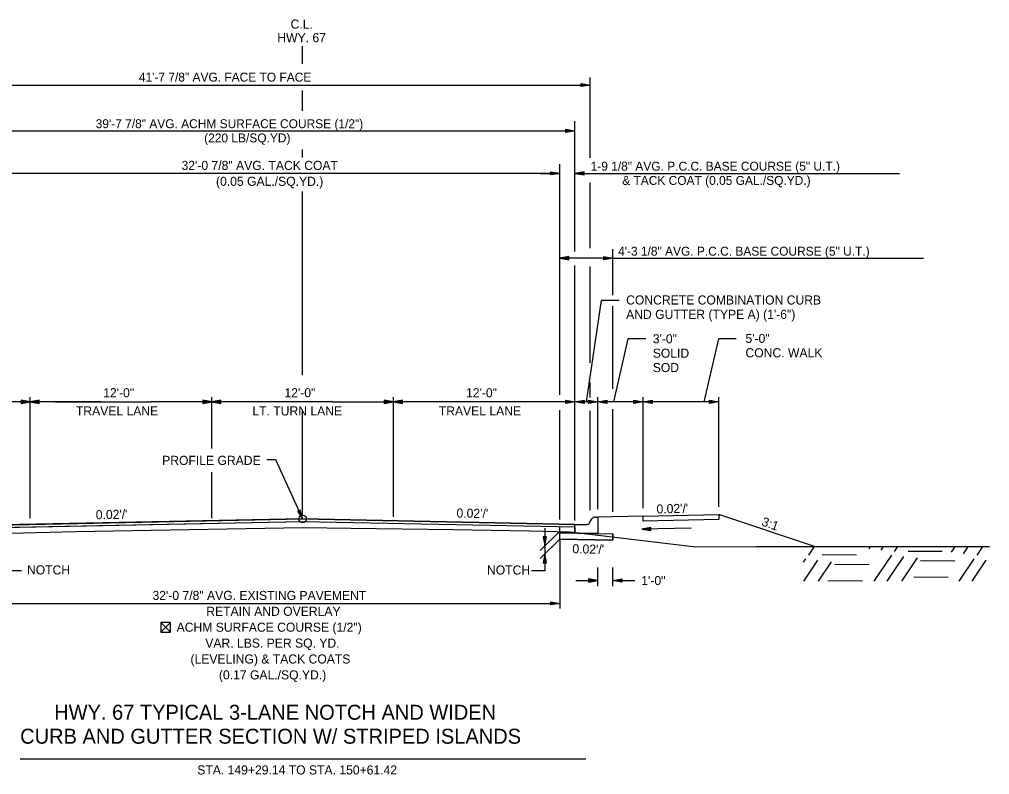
# Model space of a CAD drawing. Extents: x 1001270 to 1003428, y 1840152 to 1842912.
# Drawn here: x 1001595.7 to 1001659.8, y 1842014.9 to 1842064.9 of the extents above; entities that cross this region are included whole.
import ezdxf

# ---------------------------------------------------------------- set-up
doc = ezdxf.new("R2010")
doc.units = 0
for name, color, linetype in [('10', 7, 'Continuous'), ('19', 7, 'Continuous'), ('20', 7, 'Continuous'), ('8', 7, 'Continuous')]:
    doc.layers.add(name, color=color, linetype=linetype)

# ---------------------------------------------------------------- blocks, each defined once
blk = doc.blocks.new('TM')
at = {"layer": '8'}
for p, q in [((-120.309, 21.181), (-119.787, -20.829)), ((0, 0), (-120.309, 21.181)), ((-31.382, 2.945), (-120.176, 10.512)), ((-119.787, -20.829), (0, 0)), ((-119.911, -10.826), (-31.307, -3.057))]:
    blk.add_line(p, q, dxfattribs=at)

msp = doc.modelspace()

# ---------------------------------------------------------------- linework, layer by layer
at = {"layer": '10'}
for p, q in [((1001605.092, 1842024.997), (1001605.733, 1842024.355)), ((1001605.733, 1842024.997), (1001605.092, 1842024.355)), ((1001605.473, 1842024.355), (1001605.485, 1842024.355))]:
    msp.add_line(p, q, dxfattribs=at)
msp.add_lwpolyline([(1001605.485, 1842024.355), (1001605.733, 1842024.355), (1001605.733, 1842024.997), (1001605.092, 1842024.997), (1001605.092, 1842024.355), (1001605.473, 1842024.355)], dxfattribs=at)
at = {"layer": '19'}
for p, q in [((1001614.45, 1842061.908), (1001614.45, 1842063.094)), ((1001633.451, 1842055.7), (1001633.451, 1842061.015)), ((1001588.118, 1842060.512), (1001633.451, 1842060.512)), ((1001614.45, 1842058.815), (1001614.45, 1842060.143)), ((1001632.851, 1842060.407), (1001632.851, 1842060.617)), ((1001632.851, 1842060.617), (1001633.451, 1842060.512)), ((1001632.851, 1842060.562), (1001633.291, 1842060.527)), ((1001633.451, 1842060.512), (1001632.851, 1842060.407)), ((1001633.291, 1842060.497), (1001632.851, 1842060.457)), ((1001632.45, 1842049.512), (1001632.45, 1842058.137)), ((1001589.117, 1842057.485), (1001632.45, 1842057.485)), ((1001631.851, 1842057.38), (1001631.851, 1842057.59)), ((1001631.851, 1842057.59), (1001632.451, 1842057.485)), ((1001631.851, 1842057.535), (1001632.291, 1842057.5)), ((1001632.451, 1842057.485), (1001631.851, 1842057.38)), ((1001632.291, 1842057.47), (1001631.851, 1842057.43)), ((1001614.45, 1842055.714), (1001614.45, 1842056.258)), ((1001631.447, 1842040.046), (1001631.447, 1842055.277)), ((1001594.117, 1842054.679), (1001631.446, 1842054.679)), ((1001630.118, 1842054.677), (1001631.447, 1842054.677)), ((1001630.846, 1842054.574), (1001630.846, 1842054.784)), ((1001630.846, 1842054.784), (1001631.446, 1842054.679)), ((1001630.846, 1842054.729), (1001631.286, 1842054.694)), ((1001631.446, 1842054.679), (1001630.846, 1842054.574)), ((1001631.286, 1842054.664), (1001630.846, 1842054.624)), ((1001630.847, 1842054.572), (1001630.847, 1842054.782)), ((1001630.847, 1842054.782), (1001631.447, 1842054.677)), ((1001630.847, 1842054.727), (1001631.287, 1842054.692)), ((1001631.447, 1842054.677), (1001630.847, 1842054.572)), ((1001631.287, 1842054.662), (1001630.847, 1842054.622)), ((1001633.049, 1842054.782), (1001632.449, 1842054.677)), ((1001632.449, 1842054.677), (1001633.049, 1842054.572)), ((1001632.451, 1842054.677), (1001653.897, 1842054.677)), ((1001633.049, 1842054.727), (1001632.609, 1842054.692)), ((1001632.609, 1842054.662), (1001633.049, 1842054.622)), ((1001633.049, 1842054.572), (1001633.049, 1842054.782)), ((1001633.451, 1842049.734), (1001633.451, 1842054.073)), ((1001614.45, 1842041.341), (1001614.45, 1842053.475)), ((1001632.047, 1842049.182), (1001631.447, 1842049.077)), ((1001632.047, 1842049.127), (1001631.607, 1842049.092)), ((1001632.047, 1842048.972), (1001632.047, 1842049.182)), ((1001634.35, 1842048.972), (1001634.35, 1842049.182)), ((1001634.35, 1842049.182), (1001634.95, 1842049.077)), ((1001634.35, 1842049.127), (1001634.79, 1842049.092)), ((1001634.95, 1842046.63), (1001634.95, 1842049.677)), ((1001634.95, 1842049.077), (1001631.447, 1842049.077)), ((1001631.447, 1842049.077), (1001632.047, 1842048.972)), ((1001631.607, 1842049.062), (1001632.047, 1842049.022)), ((1001632.45, 1842031.727), (1001632.45, 1842048.58)), ((1001633.451, 1842042.162), (1001633.451, 1842048.53)), ((1001634.95, 1842049.077), (1001634.35, 1842048.972)), ((1001634.79, 1842049.062), (1001634.35, 1842049.022)), ((1001634.95, 1842049.077), (1001655.48, 1842049.077)), ((1001634.181, 1842046.267), (1001633.193, 1842039.576)), ((1001635.36, 1842046.267), (1001634.181, 1842046.267)), ((1001634.95, 1842040.43), (1001634.95, 1842045.895)), ((1001635.945, 1842043.733), (1001634.988, 1842039.576)), ((1001637.124, 1842043.733), (1001635.945, 1842043.733)), ((1001641.927, 1842043.733), (1001640.971, 1842039.576)), ((1001643.106, 1842043.733), (1001641.927, 1842043.733)), ((1001633.451, 1842039.868), (1001633.451, 1842040.863)), ((1001601.117, 1842039.576), (1001589.117, 1842039.576)), ((1001595.85, 1842039.681), (1001595.85, 1842039.471)), ((1001596.45, 1842039.576), (1001595.85, 1842039.681)), ((1001596.29, 1842039.591), (1001595.85, 1842039.626)), ((1001595.85, 1842039.471), (1001596.45, 1842039.576)), ((1001595.85, 1842039.521), (1001596.29, 1842039.561)), ((1001596.45, 1842031.887), (1001596.45, 1842039.876)), ((1001597.05, 1842039.681), (1001596.45, 1842039.576)), ((1001596.45, 1842039.576), (1001597.05, 1842039.471)), ((1001597.05, 1842039.626), (1001596.61, 1842039.591)), ((1001596.61, 1842039.561), (1001597.05, 1842039.521)), ((1001597.05, 1842039.471), (1001597.05, 1842039.681)), ((1001598.132, 1842039.576), (1001604.45, 1842039.576)), ((1001616.45, 1842039.576), (1001604.45, 1842039.576)), ((1001607.85, 1842039.681), (1001607.85, 1842039.471)), ((1001608.45, 1842039.576), (1001607.85, 1842039.681)), ((1001608.29, 1842039.591), (1001607.85, 1842039.626)), ((1001607.85, 1842039.471), (1001608.45, 1842039.576)), ((1001607.85, 1842039.521), (1001608.29, 1842039.561)), ((1001608.45, 1842036.493), (1001608.45, 1842039.876)), ((1001609.05, 1842039.681), (1001608.45, 1842039.576)), ((1001608.45, 1842039.576), (1001609.05, 1842039.471)), ((1001609.05, 1842039.626), (1001608.61, 1842039.591)), ((1001608.61, 1842039.561), (1001609.05, 1842039.521)), ((1001609.05, 1842039.471), (1001609.05, 1842039.681)), ((1001616.45, 1842039.576), (1001620.45, 1842039.576)), ((1001619.85, 1842039.681), (1001619.85, 1842039.471)), ((1001620.45, 1842039.576), (1001619.85, 1842039.681)), ((1001620.29, 1842039.591), (1001619.85, 1842039.626)), ((1001619.85, 1842039.471), (1001620.45, 1842039.576)), ((1001619.85, 1842039.521), (1001620.29, 1842039.561)), ((1001620.45, 1842031.967), (1001620.45, 1842039.876)), ((1001621.05, 1842039.681), (1001620.45, 1842039.576)), ((1001632.45, 1842039.576), (1001620.45, 1842039.576)), ((1001620.45, 1842039.576), (1001621.05, 1842039.471)), ((1001621.05, 1842039.626), (1001620.61, 1842039.591)), ((1001620.61, 1842039.561), (1001621.05, 1842039.521)), ((1001621.05, 1842039.471), (1001621.05, 1842039.681)), ((1001631.85, 1842039.471), (1001631.85, 1842039.681)), ((1001631.85, 1842039.681), (1001632.45, 1842039.576)), ((1001631.85, 1842039.626), (1001632.29, 1842039.591)), ((1001632.45, 1842039.576), (1001631.85, 1842039.471)), ((1001632.29, 1842039.561), (1001631.85, 1842039.521)), ((1001632.45, 1842031.727), (1001632.45, 1842039.876)), ((1001632.45, 1842039.576), (1001633.05, 1842039.681)), ((1001641.95, 1842039.576), (1001632.45, 1842039.576)), ((1001633.05, 1842039.471), (1001632.45, 1842039.576)), ((1001632.61, 1842039.591), (1001633.05, 1842039.626)), ((1001633.05, 1842039.521), (1001632.61, 1842039.561)), ((1001633.05, 1842039.681), (1001633.05, 1842039.471)), ((1001633.35, 1842039.471), (1001633.35, 1842039.681)), ((1001633.35, 1842039.681), (1001633.95, 1842039.576)), ((1001633.35, 1842039.626), (1001633.79, 1842039.591)), ((1001633.95, 1842039.576), (1001633.35, 1842039.471)), ((1001633.79, 1842039.561), (1001633.35, 1842039.521)), ((1001633.95, 1842032.477), (1001633.95, 1842039.876)), ((1001633.95, 1842039.576), (1001634.55, 1842039.681)), ((1001634.55, 1842039.471), (1001633.95, 1842039.576)), ((1001634.11, 1842039.591), (1001634.55, 1842039.626)), ((1001634.55, 1842039.521), (1001634.11, 1842039.561)), ((1001634.55, 1842039.681), (1001634.55, 1842039.471)), ((1001636.35, 1842039.471), (1001636.35, 1842039.681)), ((1001636.35, 1842039.681), (1001636.95, 1842039.576)), ((1001636.35, 1842039.626), (1001636.79, 1842039.591)), ((1001636.95, 1842039.576), (1001636.35, 1842039.471)), ((1001636.79, 1842039.561), (1001636.35, 1842039.521)), ((1001636.95, 1842032.537), (1001636.95, 1842039.876)), ((1001636.95, 1842039.576), (1001637.55, 1842039.681)), ((1001637.55, 1842039.471), (1001636.95, 1842039.576)), ((1001637.11, 1842039.591), (1001637.55, 1842039.626)), ((1001637.55, 1842039.521), (1001637.11, 1842039.561)), ((1001637.55, 1842039.681), (1001637.55, 1842039.471)), ((1001641.35, 1842039.471), (1001641.35, 1842039.681)), ((1001641.35, 1842039.681), (1001641.95, 1842039.576)), ((1001641.35, 1842039.626), (1001641.79, 1842039.591)), ((1001641.95, 1842039.576), (1001641.35, 1842039.471)), ((1001641.79, 1842039.561), (1001641.35, 1842039.521)), ((1001641.95, 1842032.637), (1001641.95, 1842039.876)), ((1001614.45, 1842032.087), (1001614.45, 1842039.014)), ((1001631.447, 1842031.8), (1001631.447, 1842039.023)), ((1001633.451, 1842032.407), (1001633.451, 1842038.992)), ((1001634.95, 1842032.311), (1001634.95, 1842039.087)), ((1001608.45, 1842031.887), (1001608.45, 1842034.922)), ((1001589.117, 1842031.33), (1001614.45, 1842031.837)), ((1001614.296, 1842032.426), (1001614.106, 1842032.339)), ((1001614.106, 1842032.339), (1001614.45, 1842031.837)), ((1001614.149, 1842032.355), (1001614.369, 1842031.977)), ((1001614.393, 1842031.986), (1001614.249, 1842032.399)), ((1001614.45, 1842031.837), (1001614.296, 1842032.426)), ((1001614.45, 1842031.837), (1001632.45, 1842031.477)), ((1001633.421, 1842031.586), (1001633.567, 1842031.838)), ((1001633.783, 1842031.962), (1001633.95, 1842031.962)), ((1001636.951, 1842032.023), (1001633.95, 1842031.962)), ((1001633.95, 1842031.962), (1001633.95, 1842031.629)), ((1001636.951, 1842032.022), (1001641.95, 1842032.122)), ((1001636.951, 1842031.689), (1001636.951, 1842032.022)), ((1001636.951, 1842032.022), (1001636.951, 1842032.022)), ((1001648.286, 1842030.01), (1001641.95, 1842032.122)), ((1001641.95, 1842032.122), (1001641.95, 1842031.789)), ((1001589.117, 1842031.164), (1001614.45, 1842031.67)), ((1001614.45, 1842031.67), (1001632.45, 1842031.31)), ((1001631.447, 1842030.497), (1001631.447, 1842031.33)), ((1001631.447, 1842031.33), (1001632.45, 1842031.31)), ((1001631.447, 1842030.914), (1001631.447, 1842031.33)), ((1001631.447, 1842031.33), (1001631.447, 1842031.33)), ((1001632.45, 1842031.477), (1001632.734, 1842031.471)), ((1001632.45, 1842031.31), (1001632.45, 1842030.897)), ((1001632.734, 1842031.471), (1001632.734, 1842031.471)), ((1001632.734, 1842031.471), (1001632.734, 1842031.471)), ((1001632.734, 1842031.471), (1001633.2, 1842031.462)), ((1001633.95, 1842031.629), (1001633.95, 1842031.447)), ((1001633.95, 1842031.447), (1001633.95, 1842030.867)), ((1001641.95, 1842031.789), (1001636.951, 1842031.689)), ((1001631.447, 1842031.028), (1001630.147, 1842029.755)), ((1001630.561, 1842030.658), (1001630.351, 1842030.658)), ((1001630.351, 1842030.658), (1001630.456, 1842030.058)), ((1001630.406, 1842030.658), (1001630.441, 1842030.218)), ((1001630.456, 1842030.058), (1001630.561, 1842030.658)), ((1001630.471, 1842030.218), (1001630.511, 1842030.658)), ((1001631.447, 1842030.914), (1001632.45, 1842030.894)), ((1001631.447, 1842030.914), (1001634.95, 1842030.847)), ((1001631.447, 1842030.497), (1001631.447, 1842030.914)), ((1001631.447, 1842030.914), (1001631.447, 1842030.914)), ((1001632.45, 1842030.897), (1001631.447, 1842030.914)), ((1001633.95, 1842030.867), (1001632.45, 1842030.897)), ((1001633.95, 1842030.867), (1001634.95, 1842030.847)), ((1001634.95, 1842030.427), (1001634.95, 1842030.847)), ((1001634.95, 1842030.847), (1001634.95, 1842030.427)), ((1001631.447, 1842030.497), (1001630.147, 1842029.225)), ((1001631.447, 1842030.497), (1001631.447, 1842025.91)), ((1001631.447, 1842030.497), (1001634.95, 1842030.427)), ((1001634.95, 1842030.427), (1001631.447, 1842030.497)), ((1001647.895, 1842029.436), (1001648.286, 1842030.019)), ((1001651.88, 1842029.87), (1001651.986, 1842030.02)), ((1001652.675, 1842029.778), (1001652.841, 1842030.022)), ((1001653.57, 1842029.686), (1001653.796, 1842030.025)), ((1001657.334, 1842029.63), (1001657.596, 1842030.026)), ((1001658.129, 1842029.538), (1001658.461, 1842030.027)), ((1001659.024, 1842029.446), (1001659.405, 1842030.02)), ((1001630.456, 1842029.528), (1001630.351, 1842028.928)), ((1001630.441, 1842029.368), (1001630.401, 1842028.928)), ((1001630.561, 1842028.928), (1001630.456, 1842029.528)), ((1001630.506, 1842028.928), (1001630.471, 1842029.368)), ((1001648.783, 1842029.475), (1001651.043, 1842029.453)), ((1001652.232, 1842027.723), (1001653.384, 1842029.444)), ((1001653.087, 1842027.725), (1001654.179, 1842029.352)), ((1001654.042, 1842027.727), (1001655.074, 1842029.26)), ((1001654.458, 1842029.715), (1001656.718, 1842029.704)), ((1001630.351, 1842028.928), (1001630.561, 1842028.928)), ((1001633.95, 1842027.394), (1001633.95, 1842028.632)), ((1001634.95, 1842027.394), (1001634.95, 1842028.632)), ((1001647.555, 1842028.968), (1001647.709, 1842029.193)), ((1001647.577, 1842027.719), (1001648.504, 1842029.102)), ((1001648.532, 1842027.721), (1001649.399, 1842029.009)), ((1001649.623, 1842028.846), (1001651.883, 1842028.824)), ((1001655.288, 1842029.087), (1001657.558, 1842029.074)), ((1001657.842, 1842027.728), (1001658.838, 1842029.204)), ((1001658.697, 1842027.731), (1001659.633, 1842029.112)), ((1001595.023, 1842028.425), (1001595.887, 1842028.425)), ((1001630.456, 1842028.4), (1001629.582, 1842028.4)), ((1001654.846, 1842028.017), (1001657.105, 1842027.995)), ((1001632.501, 1842027.772), (1001633.95, 1842027.772)), ((1001632.501, 1842027.772), (1001633.95, 1842027.772)), ((1001633.35, 1842027.877), (1001633.35, 1842027.667)), ((1001633.95, 1842027.772), (1001633.35, 1842027.877)), ((1001633.35, 1842027.877), (1001633.35, 1842027.667)), ((1001633.95, 1842027.772), (1001633.35, 1842027.877)), ((1001633.79, 1842027.787), (1001633.35, 1842027.822)), ((1001633.79, 1842027.787), (1001633.35, 1842027.822)), ((1001633.35, 1842027.667), (1001633.95, 1842027.772)), ((1001633.35, 1842027.667), (1001633.95, 1842027.772)), ((1001633.35, 1842027.717), (1001633.79, 1842027.757)), ((1001633.35, 1842027.717), (1001633.79, 1842027.757)), ((1001634.95, 1842027.772), (1001635.55, 1842027.877)), ((1001634.95, 1842027.772), (1001635.55, 1842027.877)), ((1001635.55, 1842027.667), (1001634.95, 1842027.772)), ((1001634.95, 1842027.772), (1001636.399, 1842027.772)), ((1001635.55, 1842027.667), (1001634.95, 1842027.772)), ((1001634.95, 1842027.772), (1001636.399, 1842027.772)), ((1001635.11, 1842027.787), (1001635.55, 1842027.822)), ((1001635.11, 1842027.787), (1001635.55, 1842027.822)), ((1001635.55, 1842027.717), (1001635.11, 1842027.757)), ((1001635.55, 1842027.717), (1001635.11, 1842027.757)), ((1001635.55, 1842027.877), (1001635.55, 1842027.667)), ((1001635.55, 1842027.877), (1001635.55, 1842027.667)), ((1001649.17, 1842027.766), (1001651.441, 1842027.754)), ((1001594.117, 1842026.258), (1001631.447, 1842026.258)), ((1001630.847, 1842026.153), (1001630.847, 1842026.363)), ((1001630.847, 1842026.363), (1001631.447, 1842026.258)), ((1001630.847, 1842026.308), (1001631.287, 1842026.273)), ((1001631.447, 1842026.258), (1001630.847, 1842026.153)), ((1001631.287, 1842026.243), (1001630.847, 1842026.203)), ((1001595.788, 1842015.991), (1001633.174, 1842015.991)), ((1001599.622, 1842015.991), (1001629.354, 1842015.991))]:
    msp.add_line(p, q, dxfattribs=at)
for points in [[(1001612.084, 1842035.769), (1001612.654, 1842035.769), (1001614.45, 1842031.837)], [(1001560.23, 1842034.4), (1001572.889, 1842034.386), (1001575.072, 1842034.166), (1001576.768, 1842033.894), (1001578.883, 1842032.583), (1001582.074, 1842031.462), (1001587.364, 1842031.607), (1001587.963, 1842031.615), (1001588.367, 1842031.161), (1001589.117, 1842031.195), (1001589.117, 1842030.738), (1001599.45, 1842030.999), (1001614.46, 1842031.276)], [(1001614.46, 1842031.276), (1001617.671, 1842031.225), (1001624.385, 1842031.132), (1001629.45, 1842031.046), (1001632.131, 1842030.984)], [(1001630.456, 1842031.224), (1001630.456, 1842028.4)], [(1001632.45, 1842030.897), (1001632.45, 1842031.061), (1001632.45, 1842031.31), (1001632.45, 1842031.477)], [(1001632.131, 1842030.984), (1001640.43, 1842029.994), (1001644.452, 1842030.007), (1001659.849, 1842030.009)]]:
    msp.add_lwpolyline(points, dxfattribs=at)
msp.add_lwpolyline([(1001614.45, 1842031.837), (1001589.117, 1842031.33), (1001589.117, 1842031.164), (1001614.45, 1842031.67), (1001632.45, 1842031.31), (1001632.45, 1842031.477)], close=True, dxfattribs=at)
msp.add_circle((1001614.45, 1842031.837), 0.25, dxfattribs=at)
for centre, start, end in [((1001633.783, 1842031.712), 90, 149.8381), ((1001633.205, 1842031.712), 268.85424, 329.83652)]:
    msp.add_arc(centre, 0.25, start, end, dxfattribs=at)
at = {"layer": '20'}
msp.add_line((1001640.131, 1842031.221), (1001636.861, 1842031.158), dxfattribs=at)

# ---------------------------------------------------------------- block references
at = {"layer": '19', "xscale": 0.0050063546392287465, "yscale": 0.005006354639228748, "rotation": -178.8817897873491}
msp.add_blockref('TM', (1001636.86, 1842031.161), dxfattribs=at)

# ---------------------------------------------------------------- texts
at = {"layer": '19'}
for s, height, p in [('C.L.', 0.6, (1001613.662, 1842064.243)), ('HWY. 67', 0.6, (1001612.783, 1842063.343)), ('41\'-7 7/8" AVG. FACE TO FACE', 0.59001, (1001603.633, 1842060.743)), ('39\'-7 7/8" AVG. ACHM SURFACE COURSE (1/2")', 0.59001, (1001600.779, 1842057.663)), ('(220 LB/SQ.YD)', 0.59001, (1001607.948, 1842056.723)), ('1-9 1/8" AVG. P.C.C. BASE COURSE (5" U.T.)', 0.59001, (1001633.486, 1842054.855)), ('& TACK COAT (0.05 GAL./SQ.YD.)', 0.59001, (1001635.572, 1842053.915)), ('4\'-3 1/8" AVG. P.C.C. BASE COURSE (5" U.T.)', 0.59001, (1001635.297, 1842049.236)), ('CONCRETE COMBINATION CURB', 0.6, (1001635.832, 1842046.009)), ('AND GUTTER (TYPE A) (1\'-6")', 0.6, (1001635.832, 1842045.059)), ('3\'-0"', 0.6, (1001637.59, 1842043.441)), ('5\'-0"', 0.6, (1001643.717, 1842043.468)), ('SOLID ', 0.6, (1001637.59, 1842042.491)), ('CONC. WALK', 0.6, (1001643.717, 1842042.518)), ('SOD', 0.6, (1001637.59, 1842041.541)), ('12\'-0"', 0.6, (1001601.275, 1842039.876)), ('12\'-0"', 0.6, (1001613.252, 1842039.876)), ('12\'-0"', 0.6, (1001625.252, 1842039.876)), ('TRAVEL LANE', 0.6, (1001599.473, 1842038.676)), ('LT. TURN LANE', 0.6, (1001611.133, 1842038.676)), ('TRAVEL LANE', 0.6, (1001623.45, 1842038.676)), ('PROFILE GRADE', 0.6, (1001605.171, 1842035.407)), ('NOTCH', 0.6, (1001596.238, 1842028.168)), ('NOTCH', 0.6, (1001626.636, 1842028.162))]:
    msp.add_text(s, height=height, dxfattribs=at).set_placement(p)
for s, height, rotation, p in [('32\'-0 7/8" AVG. TACK COAT', 0.6, 360, (1001606.45, 1842054.902)), ('(0.05 GAL./SQ.YD.)', 0.6, 360, (1001608.73, 1842053.852)), ("0.02'/'", 0.6, 1.14576, (1001600.792, 1842031.813)), ("0.02'/'", 0.6, 358.85424, (1001624.616, 1842031.932)), ("0.02'/'", 0.6, 1.42975, (1001637.847, 1842032.195)), ('3:1', 0.6, 340.49426, (1001644.734, 1842031.418)), ("0.02'/'", 0.6, 358.85424, (1001632.275, 1842029.567)), ('1\'-0"', 0.6, 360, (1001636.834, 1842027.464)), ('32\'-0 7/8" AVG. EXISTING PAVEMENT', 0.6, 360, (1001604.532, 1842026.48)), ('RETAIN AND OVERLAY', 0.6, 360, (1001608.087, 1842025.43)), ('ACHM SURFACE COURSE (1/2")', 0.6, 360, (1001606.127, 1842024.38)), ('VAR. LBS. PER SQ. YD.', 0.6, 360, (1001608.021, 1842023.33)), ('(LEVELING) & TACK COATS', 0.6, 360, (1001607.043, 1842022.28)), ('(0.17 GAL./SQ.YD.)', 0.6, 360, (1001608.923, 1842021.23)), ('HWY. 67 TYPICAL 3-LANE NOTCH AND WIDEN ', 0.98999, 359.99538, (1001598.037, 1842018.565)), ('CURB AND GUTTER SECTION W/ STRIPED ISLANDS', 0.98999, 359.99538, (1001595.788, 1842016.981)), ('STA. 149+29.14 TO STA. 150+61.42', 0.6, 359.99538, (1001607.492, 1842014.948))]:
    msp.add_text(s, height=height, rotation=rotation, dxfattribs=at).set_placement(p)

doc.saveas('drawing.dxf')
